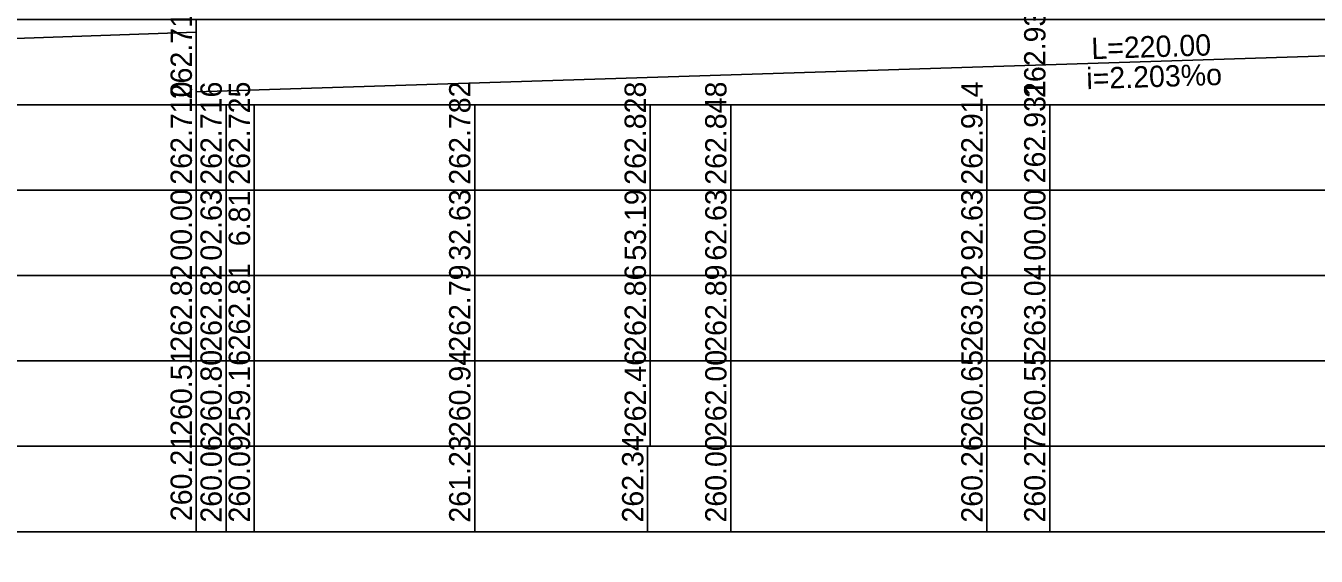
# Model space of a CAD drawing. Extents: x 6445630 to 6518227, y 5499240 to 5511716.
# Drawn here: x 6454211.2 to 6454362.4, y 5508168.4 to 5508230.5 of the extents above; entities that cross this region are included whole.
import ezdxf

# ---------------------------------------------------------------- set-up
doc = ezdxf.new("R2010")
doc.units = 0
for name, color, linetype in [('TOR_PROF-tabelka-odleglosci T1', 7, 'Continuous'), ('TOR_PROF-tabelka-pochylenia proj T1', 7, 'Continuous'), ('TOR_PROF-tabelka-rowyT1', 7, 'Continuous'), ('TOR_PROF-tabelka-rzedne istn T1', 7, 'Continuous'), ('TOR_PROF-tabelka-rzedne proj T1', 7, 'Continuous'), ('TOR_PROF-tabelka-teren istniejacy T1', 7, 'Continuous')]:
    doc.layers.add(name, color=color, linetype=linetype)

msp = doc.modelspace()

# ---------------------------------------------------------------- linework, layer by layer
at = {"layer": 'TOR_PROF-tabelka-odleglosci T1'}
msp.add_lwpolyline([(6452331.21, 5508201.29), (6454631.21, 5508201.29), (6454631.21, 5508211.29), (6452331.21, 5508211.29)], close=True, dxfattribs=at)
for points in [[(6454231.21, 5508201.29), (6454231.21, 5508211.29)], [(6454234.71, 5508201.29), (6454234.71, 5508211.29)], [(6454238.02, 5508201.29), (6454238.02, 5508211.29)], [(6454263.84, 5508201.29), (6454263.84, 5508211.29)], [(6454284.4, 5508201.29), (6454284.4, 5508211.29)], [(6454293.84, 5508201.29), (6454293.84, 5508211.29)], [(6454323.84, 5508201.29), (6454323.84, 5508211.29)], [(6454331.21, 5508201.29), (6454331.21, 5508211.29)]]:
    msp.add_lwpolyline(points, dxfattribs=at)
at = {"layer": 'TOR_PROF-tabelka-pochylenia proj T1'}
msp.add_lwpolyline([(6452331.21, 5508221.29), (6454631.21, 5508221.29), (6454631.21, 5508231.29), (6452331.21, 5508231.29)], close=True, dxfattribs=at)
for points in [[(6454231.21, 5508221.29), (6454231.21, 5508231.29)], [(6454031.21, 5508222.79), (6454231.21, 5508229.79)], [(6454231.21, 5508222.79), (6454451.21, 5508229.79)]]:
    msp.add_lwpolyline(points, dxfattribs=at)
at = {"layer": 'TOR_PROF-tabelka-rowyT1'}
msp.add_lwpolyline([(6452331.21, 5508161.29), (6454631.21, 5508161.29), (6454631.21, 5508171.29), (6452331.21, 5508171.29)], close=True, dxfattribs=at)
at = {"layer": 'TOR_PROF-tabelka-rzedne istn T1'}
msp.add_lwpolyline([(6452331.21, 5508191.29), (6454631.21, 5508191.29), (6454631.21, 5508201.29), (6452331.21, 5508201.29)], close=True, dxfattribs=at)
for points in [[(6454231.21, 5508191.29), (6454231.21, 5508201.29)], [(6454234.71, 5508191.29), (6454234.71, 5508201.29)], [(6454238.02, 5508191.29), (6454238.02, 5508201.29)], [(6454238.02, 5508191.29), (6454238.02, 5508201.29)], [(6454263.84, 5508191.29), (6454263.84, 5508201.29)], [(6454284.4, 5508191.29), (6454284.4, 5508201.29)], [(6454284.4, 5508191.29), (6454284.4, 5508201.29)], [(6454293.84, 5508191.29), (6454293.84, 5508201.29)], [(6454323.84, 5508191.29), (6454323.84, 5508201.29)], [(6454331.21, 5508191.29), (6454331.21, 5508201.29)], [(6454238.02, 5508171.29), (6454238.02, 5508181.29)]]:
    msp.add_lwpolyline(points, dxfattribs=at)
at = {"layer": 'TOR_PROF-tabelka-rzedne proj T1'}
msp.add_lwpolyline([(6452331.21, 5508211.29), (6454631.21, 5508211.29), (6454631.21, 5508221.29), (6452331.21, 5508221.29)], close=True, dxfattribs=at)
for points in [[(6454231.21, 5508211.29), (6454231.21, 5508221.29)], [(6454234.71, 5508211.29), (6454234.71, 5508221.29)], [(6454238.02, 5508211.29), (6454238.02, 5508221.29)], [(6454263.84, 5508211.29), (6454263.84, 5508221.29)], [(6454284.4, 5508211.29), (6454284.4, 5508221.29)], [(6454293.84, 5508211.29), (6454293.84, 5508221.29)], [(6454323.84, 5508211.29), (6454323.84, 5508221.29)], [(6454331.21, 5508211.29), (6454331.21, 5508221.29)]]:
    msp.add_lwpolyline(points, dxfattribs=at)
at = {"layer": 'TOR_PROF-tabelka-teren istniejacy T1'}
for points in [[(6452331.21, 5508181.29), (6454631.21, 5508181.29), (6454631.21, 5508191.29), (6452331.21, 5508191.29)], [(6452331.21, 5508171.29), (6454631.21, 5508171.29), (6454631.21, 5508181.29), (6452331.21, 5508181.29)], [(6452331.21, 5508171.29), (6454631.21, 5508171.29), (6454631.21, 5508181.29), (6452331.21, 5508181.29)]]:
    msp.add_lwpolyline(points, close=True, dxfattribs=at)
for points in [[(6454231.21, 5508181.29), (6454231.21, 5508191.29)], [(6454234.71, 5508181.29), (6454234.71, 5508191.29)], [(6454238.02, 5508181.29), (6454238.02, 5508191.29)], [(6454238.02, 5508181.29), (6454238.02, 5508191.29)], [(6454263.84, 5508181.29), (6454263.84, 5508191.29)], [(6454284.4, 5508181.29), (6454284.4, 5508191.29)], [(6454284.4, 5508181.29), (6454284.4, 5508191.29)], [(6454293.84, 5508181.29), (6454293.84, 5508191.29)], [(6454323.84, 5508181.29), (6454323.84, 5508191.29)], [(6454331.21, 5508181.29), (6454331.21, 5508191.29)], [(6454231.21, 5508171.29), (6454231.21, 5508181.29)], [(6454231.21, 5508171.29), (6454231.21, 5508181.29)], [(6454234.71, 5508171.29), (6454234.71, 5508181.29)], [(6454234.71, 5508171.29), (6454234.71, 5508181.29)], [(6454263.84, 5508171.29), (6454263.84, 5508181.29)], [(6454263.84, 5508171.29), (6454263.84, 5508181.29)], [(6454284.1, 5508171.29), (6454284.1, 5508181.29)], [(6454284.1, 5508171.29), (6454284.1, 5508181.29)], [(6454284.1, 5508171.29), (6454284.1, 5508181.29)], [(6454284.1, 5508171.29), (6454284.1, 5508181.29)], [(6454293.84, 5508171.29), (6454293.84, 5508181.29)], [(6454293.84, 5508171.29), (6454293.84, 5508181.29)], [(6454323.84, 5508171.29), (6454323.84, 5508181.29)], [(6454323.84, 5508171.29), (6454323.84, 5508181.29)], [(6454331.21, 5508171.29), (6454331.21, 5508181.29)], [(6454331.21, 5508171.29), (6454331.21, 5508181.29)]]:
    msp.add_lwpolyline(points, dxfattribs=at)

# ---------------------------------------------------------------- texts
at = {"layer": 'TOR_PROF-tabelka-odleglosci T1'}
for s, p in [('00.00', (6454230.71, 5508203.03)), ('02.63', (6454234.21, 5508203.03)), ('6.81', (6454237.52, 5508204.72)), ('32.63', (6454263.34, 5508203.03)), ('53.19', (6454283.9, 5508203.03)), ('62.63', (6454293.34, 5508203.03)), ('92.63', (6454323.34, 5508203.03)), ('00.00', (6454330.71, 5508203.03))]:
    msp.add_text(s, height=2.5, rotation=90, dxfattribs=at).set_placement(p)
at = {"layer": 'TOR_PROF-tabelka-pochylenia proj T1'}
for s, rotation, p in [('262.710', 90, (6454230.71, 5508221.93)), ('262.931', 90, (6454330.71, 5508222.09)), ('L=220.00', 1.8224, (6454336.12, 5508226.63)), ('i=2.203%o', 1.8224, (6454335.54, 5508223.11))]:
    msp.add_text(s, height=2.5, rotation=rotation, dxfattribs=at).set_placement(p)
at = {"layer": 'TOR_PROF-tabelka-rzedne istn T1'}
for s, p in [('262.82', (6454230.71, 5508192.36)), ('262.82', (6454234.21, 5508192.36)), ('262.81', (6454237.52, 5508192.52)), ('262.79', (6454263.34, 5508192.36)), ('262.86', (6454283.9, 5508192.35)), ('262.89', (6454293.34, 5508192.36)), ('263.02', (6454323.34, 5508192.36)), ('263.04', (6454330.71, 5508192.36)), ('260.09', (6454237.52, 5508172.36))]:
    msp.add_text(s, height=2.5, rotation=90, dxfattribs=at).set_placement(p)
at = {"layer": 'TOR_PROF-tabelka-rzedne proj T1'}
for s, p in [('262.710', (6454230.71, 5508211.93)), ('262.716', (6454234.21, 5508211.92)), ('262.725', (6454237.52, 5508211.92)), ('262.782', (6454263.34, 5508211.93)), ('262.828', (6454283.9, 5508211.92)), ('262.848', (6454293.34, 5508211.92)), ('262.914', (6454323.34, 5508211.93)), ('262.931', (6454330.71, 5508212.09))]:
    msp.add_text(s, height=2.5, rotation=90, dxfattribs=at).set_placement(p)
at = {"layer": 'TOR_PROF-tabelka-teren istniejacy T1'}
for s, p in [('260.51', (6454230.71, 5508182.52)), ('260.80', (6454234.21, 5508182.36)), ('259.16', (6454237.52, 5508182.35)), ('260.94', (6454263.34, 5508182.36)), ('262.46', (6454283.9, 5508182.35)), ('262.00', (6454293.34, 5508182.36)), ('260.65', (6454323.34, 5508182.35)), ('260.55', (6454330.71, 5508182.35)), ('260.21', (6454230.71, 5508172.52)), ('260.06', (6454234.21, 5508172.35)), ('261.23', (6454263.34, 5508172.35)), ('262.34', (6454283.6, 5508172.36)), ('260.00', (6454293.34, 5508172.36)), ('260.26', (6454323.34, 5508172.35)), ('260.27', (6454330.71, 5508172.36))]:
    msp.add_text(s, height=2.5, rotation=90, dxfattribs=at).set_placement(p)

doc.saveas('drawing.dxf')
